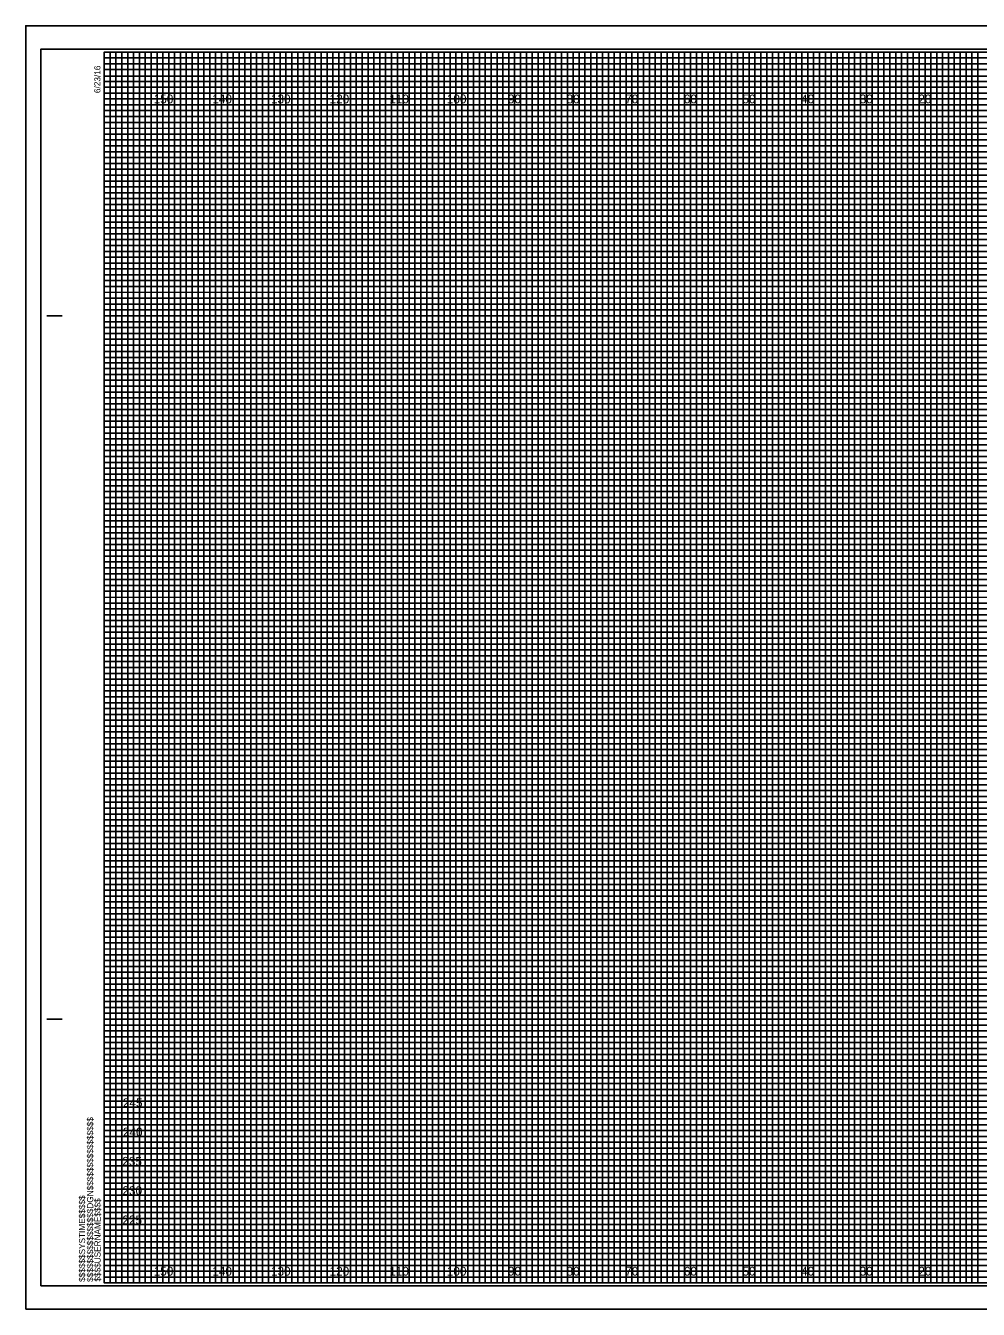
# Model space of a CAD drawing. Extents: x -13 to 323, y -5 to 654.
# Drawn here: x -13.4 to 149.1, y 435.5 to 654.5 of the extents above; entities that cross this region are included whole.
import ezdxf

# ---------------------------------------------------------------- set-up
doc = ezdxf.new("R2010")
doc.units = 0
for name, color, linetype in [('Exist Cross Section Cell', 7, 'Continuous'), ('Exist XS Center Line Elevation Label', 7, 'Continuous'), ('Exist XS Ground Line', 7, 'Continuous'), ('Prop CMT Conc Surface', 7, 'Continuous'), ('Prop CMT Concrete Structures', 7, 'Continuous'), ('Prop CMT DNC', 7, 'Continuous'), ('Prop CMT Pvmt Course 1 Wedge', 7, 'Continuous'), ('Prop CMT Pvmt Course 2', 7, 'Continuous'), ('Prop CMT Pvmt Course 2 Wedge', 7, 'Continuous'), ('Prop CMT Pvmt Course 3', 7, 'Continuous'), ('Prop CMT Subgrade Earthwork', 7, 'Continuous')]:
    doc.layers.add(name, color=color, linetype=linetype)

msp = doc.modelspace()

# ---------------------------------------------------------------- linework, layer by layer
at = {"layer": 'Exist XS Center Line Elevation Label'}
for points in [[(0, 650), (5, 650), (5, 440), (15, 440), (15, 650), (25, 650), (25, 440), (35, 440), (35, 650), (45, 650), (45, 440), (55, 440), (55, 650), (65, 650), (65, 440), (75, 440), (75, 650), (85, 650), (85, 440), (95, 440), (95, 650), (105, 650), (105, 440), (115, 440), (115, 650), (125, 650), (125, 440), (135, 440), (135, 650), (145, 650), (145, 440), (155, 440)], [(0, 645), (275, 645)], [(0, 625), (320, 625), (320, 635), (0, 635)], [(0, 605), (320, 605), (320, 615), (0, 615)], [(0, 585), (320, 585), (320, 595), (0, 595)], [(0, 565), (320, 565), (320, 575), (0, 575)], [(0, 545), (320, 545), (320, 555), (0, 555)], [(0, 525), (320, 525), (320, 535), (0, 535)], [(0, 505), (320, 505), (320, 515), (0, 515)], [(0, 485), (320, 485), (320, 495), (0, 495)], [(0, 465), (320, 465), (320, 475), (0, 475)], [(0, 445), (320, 445), (320, 455), (0, 455)]]:
    msp.add_lwpolyline(points, dxfattribs=at)
at = {"layer": 'Exist XS Ground Line'}
for p, q in [((10, 650), (0, 650)), ((10, 440), (10, 650)), ((30, 650), (20, 650)), ((20, 650), (20, 440)), ((30, 440), (30, 650)), ((50, 650), (40, 650)), ((40, 650), (40, 440)), ((50, 440), (50, 650)), ((70, 650), (60, 650)), ((60, 650), (60, 440)), ((70, 440), (70, 650)), ((90, 650), (80, 650)), ((80, 650), (80, 440)), ((90, 440), (90, 650)), ((110, 650), (100, 650)), ((100, 650), (100, 440)), ((110, 440), (110, 650)), ((130, 650), (120, 650)), ((120, 650), (120, 440)), ((130, 440), (130, 650)), ((150, 650), (140, 650)), ((140, 650), (140, 440)), ((20, 440), (10, 440)), ((40, 440), (30, 440)), ((60, 440), (50, 440)), ((80, 440), (70, 440)), ((100, 440), (90, 440)), ((120, 440), (110, 440)), ((140, 440), (130, 440))]:
    msp.add_line(p, q, dxfattribs=at)
for points in [[(0, 640), (320, 640), (320, 630), (0, 630)], [(0, 620), (320, 620), (320, 610), (0, 610)], [(0, 600), (320, 600), (320, 590), (0, 590)], [(0, 580), (320, 580), (320, 570), (0, 570)], [(0, 560), (320, 560), (320, 550), (0, 550)], [(0, 540), (320, 540), (320, 530), (0, 530)], [(0, 520), (320, 520), (320, 510), (0, 510)], [(0, 500), (320, 500), (320, 490), (0, 490)], [(0, 480), (320, 480), (320, 470), (0, 470)], [(0, 460), (320, 460), (320, 450), (0, 450)]]:
    msp.add_lwpolyline(points, dxfattribs=at)
at = {"layer": 'Prop CMT Conc Surface'}
msp.add_lwpolyline([(-13.4, 435.5), (323.3, 435.5), (323.3, 654.5), (-13.4, 654.5)], close=True, dxfattribs=at)
at = {"layer": 'Prop CMT Concrete Structures'}
for p, q in [((-9.8, 605), (-7.3, 605)), ((-9.7, 605), (-7.2, 605)), ((-9.8, 485), (-7.3, 485)), ((-9.7, 485), (-7.2, 485)), ((0, 440), (0, 440)), ((0, 440), (0, 440)), ((0, 440), (0, 440)), ((0, 440), (0, 440)), ((0, 440), (0, 440)), ((0, 440), (0, 440)), ((0, 440), (0, 440))]:
    msp.add_line(p, q, dxfattribs=at)
msp.add_lwpolyline([(320, 650), (0, 650), (0, 440), (320, 440)], close=True, dxfattribs=at)
at = {"layer": 'Prop CMT DNC'}
for points in [[(0, 440), (1, 440), (1, 650), (2, 650), (2, 440)], [(2, 440), (3, 440), (3, 650), (4, 650), (4, 440)], [(5, 440), (6, 440), (6, 650), (7, 650), (7, 440)], [(7, 440), (8, 440), (8, 650), (9, 650), (9, 440)], [(10, 440), (11, 440), (11, 650), (12, 650), (12, 440)], [(12, 440), (13, 440), (13, 650), (14, 650), (14, 440)], [(15, 440), (16, 440), (16, 650), (17, 650), (17, 440)], [(17, 440), (18, 440), (18, 650), (19, 650), (19, 440)], [(20, 440), (21, 440), (21, 650), (22, 650), (22, 440)], [(22, 440), (23, 440), (23, 650), (24, 650), (24, 440)], [(25, 440), (26, 440), (26, 650), (27, 650), (27, 440)], [(27, 440), (28, 440), (28, 650), (29, 650), (29, 440)], [(30, 440), (31, 440), (31, 650), (32, 650), (32, 440)], [(32, 440), (33, 440), (33, 650), (34, 650), (34, 440)], [(35, 440), (36, 440), (36, 650), (37, 650), (37, 440)], [(37, 440), (38, 440), (38, 650), (39, 650), (39, 440)], [(40, 440), (41, 440), (41, 650), (42, 650), (42, 440)], [(42, 440), (43, 440), (43, 650), (44, 650), (44, 440)], [(45, 440), (46, 440), (46, 650), (47, 650), (47, 440)], [(47, 440), (48, 440), (48, 650), (49, 650), (49, 440)], [(50, 440), (51, 440), (51, 650), (52, 650), (52, 440)], [(52, 440), (53, 440), (53, 650), (54, 650), (54, 440)], [(55, 440), (56, 440), (56, 650), (57, 650), (57, 440)], [(57, 440), (58, 440), (58, 650), (59, 650), (59, 440)], [(60, 440), (61, 440), (61, 650), (62, 650), (62, 440)], [(62, 440), (63, 440), (63, 650), (64, 650), (64, 440)], [(65, 440), (66, 440), (66, 650), (67, 650), (67, 440)], [(67, 440), (68, 440), (68, 650), (69, 650), (69, 440)], [(70, 440), (71, 440), (71, 650), (72, 650), (72, 440)], [(72, 440), (73, 440), (73, 650), (74, 650), (74, 440)], [(75, 440), (76, 440), (76, 650), (77, 650), (77, 440)], [(77, 440), (78, 440), (78, 650), (79, 650), (79, 440)], [(80, 440), (81, 440), (81, 650), (82, 650), (82, 440)], [(82, 440), (83, 440), (83, 650), (84, 650), (84, 440)], [(85, 440), (86, 440), (86, 650), (87, 650), (87, 440)], [(87, 440), (88, 440), (88, 650), (89, 650), (89, 440)], [(90, 440), (91, 440), (91, 650), (92, 650), (92, 440)], [(92, 440), (93, 440), (93, 650), (94, 650), (94, 440)], [(95, 440), (96, 440), (96, 650), (97, 650), (97, 440)], [(97, 440), (98, 440), (98, 650), (99, 650), (99, 440)], [(100, 440), (101, 440), (101, 650), (102, 650), (102, 440)], [(102, 440), (103, 440), (103, 650), (104, 650), (104, 440)], [(105, 440), (106, 440), (106, 650), (107, 650), (107, 440)], [(107, 440), (108, 440), (108, 650), (109, 650), (109, 440)], [(110, 440), (111, 440), (111, 650), (112, 650), (112, 440)], [(112, 440), (113, 440), (113, 650), (114, 650), (114, 440)], [(115, 440), (116, 440), (116, 650), (117, 650), (117, 440)], [(117, 440), (118, 440), (118, 650), (119, 650), (119, 440)], [(120, 440), (121, 440), (121, 650), (122, 650), (122, 440)], [(122, 440), (123, 440), (123, 650), (124, 650), (124, 440)], [(125, 440), (126, 440), (126, 650), (127, 650), (127, 440)], [(127, 440), (128, 440), (128, 650), (129, 650), (129, 440)], [(130, 440), (131, 440), (131, 650), (132, 650), (132, 440)], [(132, 440), (133, 440), (133, 650), (134, 650), (134, 440)], [(135, 440), (136, 440), (136, 650), (137, 650), (137, 440)], [(137, 440), (138, 440), (138, 650), (139, 650), (139, 440)], [(140, 440), (141, 440), (141, 650), (142, 650), (142, 440)], [(142, 440), (143, 440), (143, 650), (144, 650), (144, 440)], [(145, 440), (146, 440), (146, 650), (147, 650), (147, 440)], [(147, 440), (148, 440), (148, 650), (149, 650), (149, 440)]]:
    msp.add_lwpolyline(points, dxfattribs=at)
at = {"layer": 'Prop CMT Pvmt Course 1 Wedge'}
for p, q in [((323.3, 654.5), (-13.4, 654.5)), ((-13.4, 654.5), (-13.4, 435.5)), ((-13.4, 435.5), (323.3, 435.5))]:
    msp.add_line(p, q, dxfattribs=at)
at = {"layer": 'Prop CMT Pvmt Course 2'}
msp.add_lwpolyline([(-10.8, 439.5), (322.4, 439.5), (322.4, 650.5), (-10.8, 650.5)], close=True, dxfattribs=at)
at = {"layer": 'Prop CMT Pvmt Course 3'}
for p, q in [((10, 440), (10, 650)), ((20, 440), (20, 650)), ((30, 440), (30, 650)), ((40, 440), (40, 650)), ((50, 440), (50, 650)), ((60, 440), (60, 650)), ((70, 440), (70, 650)), ((80, 440), (80, 650)), ((90, 440), (90, 650)), ((100, 440), (100, 650)), ((110, 440), (110, 650)), ((120, 440), (120, 650)), ((130, 440), (130, 650)), ((140, 440), (140, 650)), ((0, 640), (320, 640)), ((0, 630), (320, 630)), ((0, 620), (320, 620)), ((0, 610), (320, 610)), ((0, 600), (320, 600)), ((0, 590), (320, 590)), ((0, 580), (320, 580)), ((0, 570), (320, 570)), ((0, 560), (320, 560)), ((0, 550), (320, 550)), ((0, 540), (320, 540)), ((0, 530), (320, 530)), ((0, 520), (320, 520)), ((0, 510), (320, 510)), ((0, 500), (320, 500)), ((0, 490), (320, 490)), ((0, 480), (320, 480)), ((0, 470), (320, 470)), ((0, 460), (320, 460)), ((0, 450), (320, 450))]:
    msp.add_line(p, q, dxfattribs=at)
at = {"layer": 'Prop CMT Subgrade Earthwork'}
for p, q in [((0, 649), (260, 649)), ((260, 647.98), (0, 647.98)), ((0, 647.98), (0, 647)), ((0, 647), (260, 647)), ((260, 645.89), (0, 645.89)), ((0, 645.89), (0, 644)), ((0, 644), (320, 644))]:
    msp.add_line(p, q, dxfattribs=at)
for points in [[(0, 643), (270, 643), (320, 643), (320, 642), (0, 642)], [(0, 641), (320, 641), (320, 639), (0, 639)], [(0, 638), (320, 638), (320, 637), (0, 636.98)], [(0, 636), (320, 636), (320, 634), (0, 634)], [(0, 633), (320, 633), (320, 632), (0, 632)], [(0, 631), (320, 631), (320, 629), (0, 629)], [(0, 628), (320, 628), (320, 627), (0, 627)], [(0, 626), (320, 626), (320, 624), (0, 624)], [(0, 623), (320, 623), (320, 622), (0, 622)], [(0, 621), (320, 621), (320, 619), (0, 619)], [(0, 618), (320, 618), (320, 617), (0, 617)], [(0, 616), (320, 616), (320, 613.95), (320, 613), (320, 612), (0, 612)], [(0, 614), (320, 614), (320, 613), (0, 613)], [(0, 611), (320, 611), (320, 609), (0, 609.03)], [(0, 609.03), (320, 609), (320, 608), (0, 608)], [(0, 607), (320, 607), (320, 606), (0, 606)], [(0, 604), (320, 604), (320, 603), (0, 603)], [(0, 602), (320, 602), (320, 601), (0, 601)], [(-0.07, 598.89), (320, 598.89), (320, 597.88), (-0.07, 597.88)], [(0, 597), (320, 597), (320, 596), (0, 596)], [(0, 594), (320, 594), (320, 593), (0, 593)], [(0, 592), (320, 592), (320, 591), (0, 591)], [(0, 589), (320, 589), (320, 588), (0, 588)], [(0, 587), (320, 587), (320, 586), (0, 586)], [(0, 584), (320, 584), (320, 583), (0, 583)], [(0, 582), (320, 582), (320, 581), (0, 581)], [(0, 579), (320, 579), (319.99, 577.98), (0, 578)], [(0, 577), (320, 577), (320, 576), (0, 576)], [(0, 574), (320, 574), (320, 573), (0, 573)], [(0, 572), (320, 572), (320, 571), (0, 571)], [(0, 569), (320, 569), (320, 568), (0, 568)], [(0, 567), (320, 567), (320, 566), (0, 566)], [(0, 564), (320, 564), (320, 563), (0, 563)], [(0, 562), (320, 562), (320, 561), (0, 561)], [(0, 559), (320, 559), (320, 558), (0, 558)], [(0, 556.99), (320.07, 556.91), (320, 556), (0, 556)], [(0, 554), (320, 554), (320, 553), (0, 553)], [(0, 552), (320, 552), (320, 551), (0, 551)], [(0, 549), (320, 549), (320, 548), (0, 548)], [(0, 547), (320, 547), (320, 546), (0, 546)], [(0, 544), (320, 544), (320, 543), (0, 543)], [(0, 542), (320, 542), (320, 541), (0, 541)], [(0, 539), (320, 539), (320, 538), (0, 538)], [(0, 537), (320, 537), (320, 536), (0, 536)], [(0, 534), (320, 534), (320, 533), (0, 533)], [(0, 532), (320, 532), (320, 531), (0, 531)], [(0, 529), (320, 529), (320, 528), (0, 528)], [(0, 527), (320, 527), (320, 526), (0, 526)], [(0, 524), (320, 524), (320, 523), (0, 523)], [(0, 522), (320, 522), (320, 521), (0, 521)], [(0, 519), (320, 519), (319.99, 517.98), (0, 518)], [(0, 517), (320, 517), (320, 516), (0, 516)], [(0, 514), (320, 514), (320, 513), (0, 513)], [(0, 512), (320, 512), (320, 511), (0, 511)], [(0, 509), (320, 509), (320, 508), (0, 508)], [(0, 507), (320, 507), (320, 506), (0, 506)], [(0, 504), (320, 504), (320, 503), (0, 503)], [(0, 502), (320, 502), (320, 501), (0, 501)], [(0, 499), (320, 499), (320, 498), (0, 498)], [(0, 496.99), (320.07, 496.91), (320, 496), (0, 496)], [(0, 494), (320, 494), (320, 493), (0, 493)], [(0, 492), (320, 492), (320, 491), (0, 491)], [(0, 489), (320, 489), (320, 488), (0, 488)], [(0, 487), (320, 487), (320, 486), (0, 486)], [(0, 484), (320, 484), (320, 483), (0, 483)], [(0, 482), (320, 482), (320, 481), (0, 481)], [(0, 479), (320, 479), (320, 478), (0, 478)], [(0, 477), (320, 477), (320, 476), (0, 476)], [(0, 474), (320, 474), (320, 473), (0, 473)], [(0, 472), (320, 472), (320, 471), (0, 471)], [(0, 469), (320, 469), (320, 468), (0, 468)], [(0, 467), (320, 467), (320, 466), (0, 466)], [(0, 464), (320, 464), (320, 463), (0, 463)], [(0, 462), (320, 462), (320, 461), (0, 461)], [(0, 459), (320, 459), (320, 458), (0, 458)], [(0, 457), (320, 457), (320, 456), (0, 456)], [(0, 454), (320, 454), (320, 453), (0, 453)], [(0, 452), (320, 452), (320, 451), (0, 451)], [(0, 449), (320, 449), (320, 448), (0, 448)], [(0, 447), (320, 447), (320, 446), (0, 446)], [(0, 444), (320, 444), (320, 443), (0, 443)], [(0, 442), (320, 442), (320, 441), (0, 441)]]:
    msp.add_lwpolyline(points, dxfattribs=at)

# ---------------------------------------------------------------- texts
at = {"layer": 'Exist Cross Section Cell'}
for s, p in [('150', (8.44, 641.25)), ('140', (18.44, 641.25)), ('130', (28.44, 641.25)), ('120', (38.44, 641.25)), ('110', (48.62, 641.25)), ('100', (58.44, 641.25)), ('90', (68.86, 641.25)), ('80', (78.86, 641.25)), ('70', (88.86, 641.25)), ('60', (98.86, 641.25)), ('50', (108.86, 641.25)), ('40', (118.86, 641.25)), ('30', (128.86, 641.25)), ('20', (138.86, 641.25)), ('150', (8.44, 441.25)), ('140', (18.44, 441.25)), ('130', (28.44, 441.25)), ('120', (38.44, 441.25)), ('110', (48.62, 441.25)), ('100', (58.44, 441.25)), ('90', (68.86, 441.25)), ('80', (78.86, 441.25)), ('70', (88.86, 441.25)), ('60', (98.86, 441.25)), ('50', (108.86, 441.25)), ('40', (118.86, 441.25)), ('30', (128.86, 441.25)), ('20', (138.86, 441.25))]:
    msp.add_text(s, height=1.5, dxfattribs=at).set_placement(p)
at = {"layer": 'Prop CMT Concrete Structures'}
for s, p in [('6/23/16', (-0.65, 643)), ('$$$$$$$$$$$$$$$$DGN$$$$$$$$$$$$$$$$', (-1.88, 440.18)), ('$$$$$$SYSTIME$$$$$', (-3.26, 440.18)), ('$$$$USERNAME$$$$', (-0.62, 440.23))]:
    msp.add_text(s, height=1.05, rotation=90, dxfattribs=at).set_placement(p)
at = {"layer": 'Prop CMT Pvmt Course 2 Wedge'}
for s, p in [('245', (3.18, 470)), ('240', (3.19, 465)), ('235', (3.09, 460)), ('230', (3.11, 455)), ('225', (3.1, 450))]:
    msp.add_text(s, height=1.5, dxfattribs=at).set_placement(p)

doc.saveas('drawing.dxf')
